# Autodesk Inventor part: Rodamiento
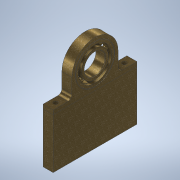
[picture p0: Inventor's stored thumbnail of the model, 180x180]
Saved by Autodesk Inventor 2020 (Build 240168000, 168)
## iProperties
Created: 2019-03
Part Number: Rodamiento
Material: Generic
Document SubType Name: Modeling
Designer: user
Density: 1 g/cm^3
Appearance: Default
Author: user
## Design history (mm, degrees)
derived "Ensamble chumacera y soporte.iam"
body "Solid1"
node "Soporte chumaceras.ipt:1"
node "Ensamble chumacera.iam:1::Base chumacera.ipt:1"
